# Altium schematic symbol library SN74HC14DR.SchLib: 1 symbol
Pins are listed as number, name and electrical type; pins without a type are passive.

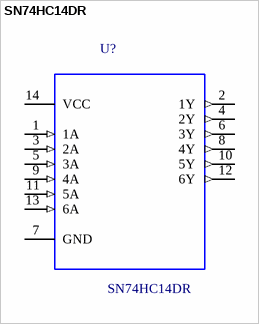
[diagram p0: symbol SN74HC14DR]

## SN74HC14DR
designator U?
Inverter Schmitt Trigger 6-Element CMOS 14-Pin SOIC T/R; MF: Texas Instruments
footprint SOIC127P600X175-14N
pins: 1 1A (in), 2 1Y (out), 3 2A (in), 4 2Y (out), 5 3A (in), 6 3Y (out), 7 GND, 8 4Y (out), 9 4A (in), 10 5Y (out), 11 5A (in), 12 6Y (out), 13 6A (in), 14 VCC (power)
